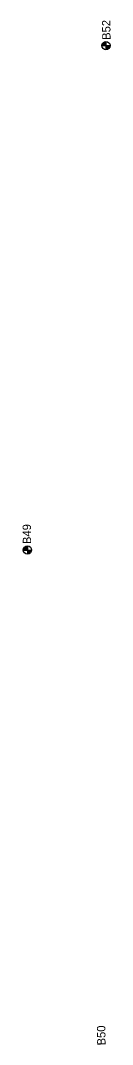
# Model space of a CAD drawing. Extents: x 345549 to 379569, y 127949 to 230467.
# Drawn here: x 360146 to 360251, y 156340 to 157564 of the extents above; entities that cross this region are included whole.
import ezdxf

# ---------------------------------------------------------------- set-up
doc = ezdxf.new("R2010")
doc.units = 0
for name, color, linetype in [('E_SOIL_BORE1 [KAPUR_CADDS_LEVELS]', 7, 'Continuous'), ('E_SOIL_BORE2 [KAPUR_CADDS_LEVELS]', 7, 'Continuous'), ('P_MARK', 7, 'Continuous')]:
    doc.layers.add(name, color=color, linetype=linetype)

msp = doc.modelspace()

# ---------------------------------------------------------------- linework, layer by layer
at = {"layer": 'P_MARK'}
for p, q in [((360240.6, 157534), (360250.6, 157534)), ((360245.6, 157539), (360245.6, 157529)), ((360151.6, 156936.2), (360151.6, 156926.2)), ((360146.6, 156931.2), (360156.6, 156931.2))]:
    msp.add_line(p, q, dxfattribs=at)
for centre in [(360245.6, 157534), (360151.6, 156931.2)]:
    msp.add_circle(centre, 5, dxfattribs=at)
for centre, radius, start, end in [((360245.6, 157534), 4.5, 89.9869, 179.9869), ((360245.6, 157534), 4, 89.9869, 179.9869), ((360245.6, 157534), 3.5, 89.9869, 179.9869), ((360245.6, 157534), 3, 89.9869, 179.9869), ((360245.6, 157534), 2.5, 89.9869, 179.9869), ((360245.6, 157534), 2, 89.9869, 179.9869), ((360245.6, 157534), 1.5, 89.9869, 179.9869), ((360245.6, 157534), 1, 89.9869, 179.9869), ((360245.6, 157534), 0.5, 89.9869, 179.9869), ((360245.6, 157534), 4.5, 269.9869, 359.9869), ((360245.6, 157534), 4, 269.9869, 359.9869), ((360245.6, 157534), 3.5, 269.9869, 359.9869), ((360245.6, 157534), 3, 269.9869, 359.9869), ((360245.6, 157534), 2.5, 269.9869, 359.9869), ((360245.6, 157534), 2, 269.9869, 359.9869), ((360245.6, 157534), 1.5, 269.9869, 359.9869), ((360245.6, 157534), 1, 269.9869, 359.9869), ((360245.6, 157534), 0.5, 269.9869, 359.9869), ((360151.6, 156931.2), 4.5, 89.9869, 179.9869), ((360151.6, 156931.2), 4, 89.9869, 179.9869), ((360151.6, 156931.2), 3.5, 89.9869, 179.9869), ((360151.6, 156931.2), 3, 89.9869, 179.9869), ((360151.6, 156931.2), 2.5, 89.9869, 179.9869), ((360151.6, 156931.2), 2, 89.9869, 179.9869), ((360151.6, 156931.2), 1.5, 89.9869, 179.9869), ((360151.6, 156931.2), 1, 89.9869, 179.9869), ((360151.6, 156931.2), 0.5, 89.9869, 179.9869), ((360151.6, 156931.2), 4.5, 269.9869, 359.9869), ((360151.6, 156931.2), 4, 269.9869, 359.9869), ((360151.6, 156931.2), 3.5, 269.9869, 359.9869), ((360151.6, 156931.2), 3, 269.9869, 359.9869), ((360151.6, 156931.2), 2.5, 269.9869, 359.9869), ((360151.6, 156931.2), 2, 269.9869, 359.9869), ((360151.6, 156931.2), 1.5, 269.9869, 359.9869), ((360151.6, 156931.2), 1, 269.9869, 359.9869), ((360151.6, 156931.2), 0.5, 269.9869, 359.9869)]:
    msp.add_arc(centre, radius, start, end, dxfattribs=at)

# ---------------------------------------------------------------- texts
at = {"layer": 'E_SOIL_BORE1 [KAPUR_CADDS_LEVELS]'}
msp.add_text('B50', height=10, rotation=90.6368, dxfattribs=at).set_placement((360245.1, 156339.2))
at = {"layer": 'E_SOIL_BORE2 [KAPUR_CADDS_LEVELS]'}
for s, p in [('B52', (360251.1, 157540.9)), ('B49', (360156.1, 156938.4))]:
    msp.add_text(s, height=10, rotation=90.6368, dxfattribs=at).set_placement(p)

doc.saveas('drawing.dxf')
